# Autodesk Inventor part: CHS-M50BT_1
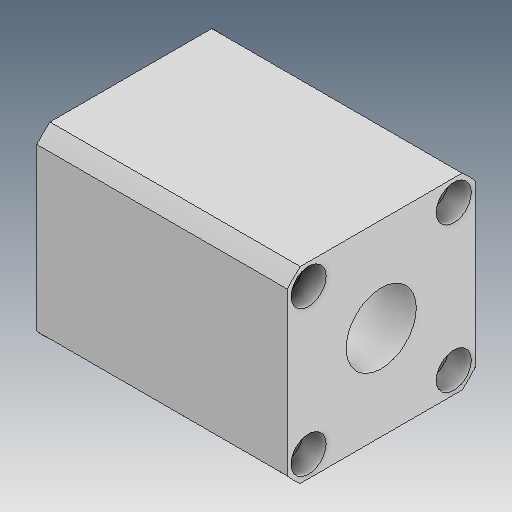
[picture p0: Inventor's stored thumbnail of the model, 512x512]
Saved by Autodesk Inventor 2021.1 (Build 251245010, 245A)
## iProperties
Created: 2019-04
Part Number: CHS-M50BT_1
Material: Ogólny
Document SubType Name: Modeling
Designer: user
Density: 1 g/cm^3
Appearance: Domyślna
Author: user
Revision Number: ÈÎºÎ
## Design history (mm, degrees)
feature "ÊäÈë1"
node "Bryła1"
